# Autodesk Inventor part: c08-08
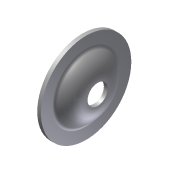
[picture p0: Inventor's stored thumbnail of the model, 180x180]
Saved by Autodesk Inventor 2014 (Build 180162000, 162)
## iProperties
Created: 2010-12
Part Number: c08-08
Document SubType Name: Modeling
Designer: Thom Tremblay
Density: 1 g/cm^3
Material: Generic
Appearance: Steel
Author: Thom Tremblay
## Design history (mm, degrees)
sketch "Sketch1"
  geometry: L1 (-1.246, 28.575)-(-1.246, 21.449); L2 (6.025, 7.188)-(6.025, 6.35); L3 (0, 0)-(18.611, 0); L4 (1.135, 28.575)-(1.135, 21.449); L5 (8.406, 7.188)-(8.406, 6.35); L6 (8.406, 6.35)-(6.025, 6.35); L7 (-1.246, 28.575)-(1.135, 28.575); A1 r 4.921 centre (3.675, 21.449) between (-1.246, 21.449) and (0.785, 17.467); A2 r 12.7 centre (-6.675, 7.188) between (6.025, 7.188) and (0.785, 17.467); A3 r 2.54 centre (3.675, 21.449) between (1.135, 21.449) and (2.183, 19.394); A4 r 15.081 centre (-6.675, 7.188) between (8.406, 7.188) and (2.183, 19.394)
  constraints: 14 end point, 8 point on circle, 5 tangent, 4 centre point, 3 parallel, 2 perpendicular, 1 vertical, 2 other
  dimensions: "d0" = 2.38125 distance between parallel lines of L4 L1; "d1" = 57.15 diameter of L1.start L3; "d2" = 12.7 diameter of L5.end L3; "d3" = 9.652 distance between parallel lines of L1 L5; "d4" = 12.7 radius of A2; "d5" = 2.54 radius of A3
revolve "Revolution1" sketch "Sketch1" stored, may be unused: angle "d6" = 90 deg
body "Solid1"
